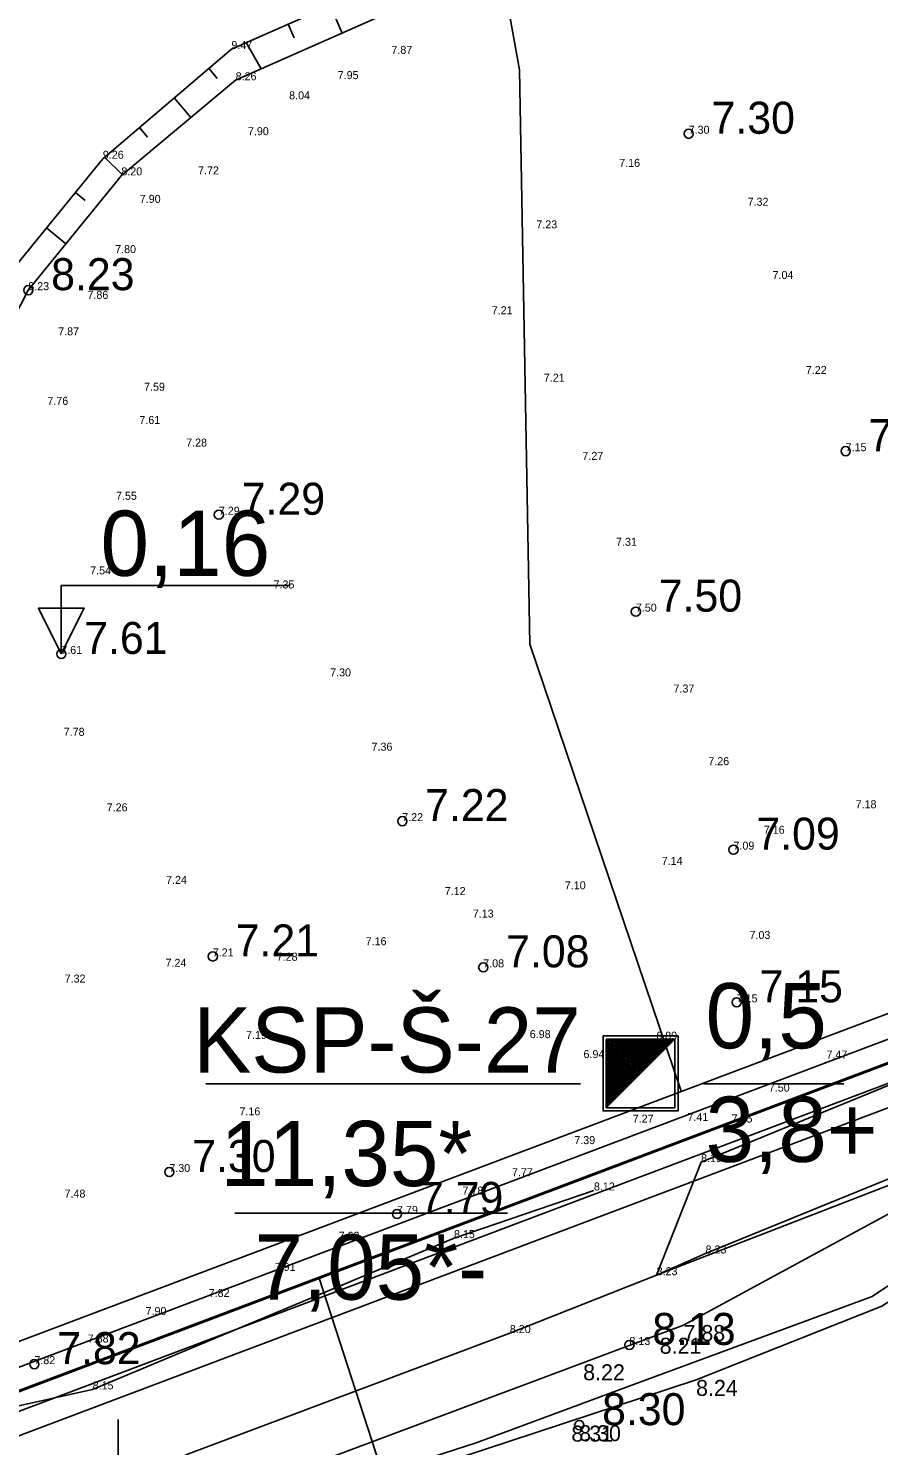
# Model space of a CAD drawing. Extents: x 433497 to 434382, y 6534486 to 6534993.
# Drawn here: x 433896.1 to 433933.2, y 6534702.9 to 6534764.8 of the extents above; entities that cross this region are included whole.
import ezdxf

# ---------------------------------------------------------------- set-up
doc = ezdxf.new("R2010")
doc.units = 0
for name, color, linetype in [('Default', 7, 'Continuous'), ('GEOLPUNKT', 7, 'Continuous'), ('jääkpaksus', 7, 'Continuous'), ('kataster', 7, 'Continuous'), ('KORGUS-EH2000', 7, 'Continuous'), ('MOOTKORG-EH2000', 7, 'Continuous'), ('PIIR', 7, 'Continuous'), ('RELJEEF', 7, 'Continuous'), ('VEEKOGU', 7, 'Continuous'), ('VORK', 7, 'Continuous')]:
    doc.layers.add(name, color=color, linetype=linetype)

msp = doc.modelspace()

# ---------------------------------------------------------------- linework, layer by layer
at = {"layer": 'Default'}
msp.add_lwpolyline([(433617.12, 6534791.025), (433632.75, 6534606.045), (434137.38, 6534796.515), (434127.69, 6534855.6), (433968.21, 6534911.925), (433942.38, 6534904.035), (433920.99, 6534907.275)], close=True, dxfattribs=at)
msp.add_lwpolyline([(433617.12, 6534791.025), (433632.75, 6534606.045), (434137.38, 6534796.515), (434127.69, 6534855.6), (433968.21, 6534911.925), (433942.38, 6534904.035), (433920.99, 6534907.275)], close=True, dxfattribs=at)
msp.add_lwpolyline([(433617.12, 6534791.025), (433632.75, 6534606.045), (434137.38, 6534796.515), (434127.69, 6534855.6), (433968.21, 6534911.925), (433942.38, 6534904.035), (433920.99, 6534907.275)], close=True, dxfattribs=at)
at = {"layer": 'GEOLPUNKT'}
for p, q in [((433921.332, 6534717.624), (433924.332, 6534720.624)), ((433921.332, 6534717.654), (433924.302, 6534720.624)), ((433921.332, 6534717.725), (433924.231, 6534720.624)), ((433921.332, 6534717.795), (433924.161, 6534720.624)), ((433921.332, 6534717.866), (433924.09, 6534720.624)), ((433921.332, 6534717.937), (433924.019, 6534720.624)), ((433921.332, 6534718.008), (433923.948, 6534720.624)), ((433921.332, 6534718.078), (433923.878, 6534720.624)), ((433921.332, 6534718.149), (433923.807, 6534720.624)), ((433921.332, 6534718.22), (433923.736, 6534720.624)), ((433921.332, 6534718.29), (433923.666, 6534720.624)), ((433921.332, 6534718.361), (433923.595, 6534720.624)), ((433921.332, 6534718.432), (433923.524, 6534720.624)), ((433921.332, 6534718.503), (433923.453, 6534720.624)), ((433921.332, 6534718.573), (433923.383, 6534720.624)), ((433921.332, 6534718.644), (433923.312, 6534720.624)), ((433921.332, 6534718.715), (433923.241, 6534720.624)), ((433921.332, 6534718.785), (433923.171, 6534720.624)), ((433921.332, 6534718.856), (433923.1, 6534720.624)), ((433921.332, 6534718.927), (433923.029, 6534720.624)), ((433921.332, 6534718.998), (433922.959, 6534720.624)), ((433921.332, 6534719.068), (433922.888, 6534720.624)), ((433921.332, 6534719.139), (433922.817, 6534720.624)), ((433921.332, 6534719.21), (433922.746, 6534720.624)), ((433921.332, 6534719.28), (433922.676, 6534720.624)), ((433921.332, 6534719.351), (433922.605, 6534720.624)), ((433921.332, 6534719.422), (433922.534, 6534720.624)), ((433921.332, 6534719.492), (433922.464, 6534720.624)), ((433921.332, 6534719.563), (433922.393, 6534720.624)), ((433921.332, 6534719.634), (433922.322, 6534720.624)), ((433921.332, 6534719.705), (433922.251, 6534720.624)), ((433921.332, 6534719.775), (433922.181, 6534720.624)), ((433921.332, 6534719.846), (433922.11, 6534720.624)), ((433921.332, 6534719.917), (433922.039, 6534720.624)), ((433921.332, 6534719.987), (433921.969, 6534720.624)), ((433921.332, 6534720.058), (433921.898, 6534720.624)), ((433921.332, 6534720.129), (433921.827, 6534720.624)), ((433921.332, 6534720.2), (433921.756, 6534720.624)), ((433921.332, 6534720.27), (433921.686, 6534720.624)), ((433921.332, 6534720.341), (433921.615, 6534720.624)), ((433921.332, 6534720.412), (433921.544, 6534720.624)), ((433921.332, 6534720.482), (433921.474, 6534720.624)), ((433921.332, 6534720.553), (433921.403, 6534720.624)), ((433922.832, 6534719.124), (433922.832, 6534719.124))]:
    msp.add_line(p, q, dxfattribs=at)
for points in [[(433921.191, 6534720.765), (433924.473, 6534720.765), (433924.473, 6534717.483), (433921.191, 6534717.483)], [(433921.332, 6534720.624), (433924.332, 6534720.624), (433924.332, 6534717.624), (433921.332, 6534717.624)]]:
    msp.add_lwpolyline(points, close=True, dxfattribs=at)
for points in [[(433903.825, 6534718.667), (433920.21, 6534718.667)], [(433925.589, 6534718.667), (433931.717, 6534718.667)], [(433905.096, 6534713.013), (433917.013, 6534713.013)]]:
    msp.add_lwpolyline(points, dxfattribs=at)
at = {"layer": 'jääkpaksus'}
msp.add_lwpolyline([(433897.514, 6534737.465), (433897.514, 6534740.465), (433907.514, 6534740.465)], dxfattribs=at)
msp.add_lwpolyline([(433897.514, 6534737.465), (433896.514, 6534739.465), (433898.514, 6534739.465)], close=True, dxfattribs=at)
at = {"layer": 'kataster'}
msp.add_lwpolyline([(433617.102, 6534791.002), (433632.769, 6534606.029), (434137.446, 6534796.469), (434127.827, 6534855.589), (433950.026, 6534918.39)], close=True, dxfattribs=at)
at = {"layer": 'KORGUS-EH2000'}
for centre in [(433924.936, 6534760.209), (433896.07, 6534753.37), (433931.794, 6534746.331), (433904.401, 6534743.551), (433922.627, 6534739.316), (433897.514, 6534737.465), (433912.416, 6534730.156), (433926.894, 6534728.909), (433904.135, 6534724.24), (433915.956, 6534723.763), (433927.033, 6534722.233), (433902.237, 6534714.815), (433912.189, 6534712.982), (433922.346, 6534707.253), (433896.337, 6534706.413), (433920.152, 6534703.746)]:
    msp.add_circle(centre, 0.2, dxfattribs=at)
at = {"layer": 'PIIR'}
msp.add_line((433908.78, 6534710.175), (433926.99, 6534654.105), dxfattribs=at)
for points in [[(433632.021, 6534604.835), (434138.248, 6534795.936), (434128.468, 6534856.135), (433968.226, 6534912.818), (433942.33, 6534904.85), (433920.952, 6534908.165), (433616.327, 6534791.524), (433632.021, 6534604.835)], [(433632.732, 6534605.959), (434137.353, 6534796.454), (434127.754, 6534855.539), (433968.208, 6534911.976), (433942.39, 6534904.031), (433921.04, 6534907.341), (433617.174, 6534790.992), (433632.732, 6534605.959)], [(433924.608, 6534718.343), (433917.99, 6534737.895), (433917.54, 6534763.005), (433913.58, 6534784.995), (433921.17, 6534796.005), (433926.99, 6534825.75), (433941, 6534841.965), (433961.01, 6534846.975), (433983.99, 6534835.44), (434035.235, 6534886.132)], [(433633.446, 6534604.304), (434134.891, 6534793.6)]]:
    msp.add_lwpolyline(points, dxfattribs=at)
for points in [[(433618.234, 6534790.327), (433921.149, 6534906.313), (433942.464, 6534903.008), (433968.187, 6534910.923), (434126.862, 6534854.794), (434136.235, 6534797.101), (433633.617, 6534607.362)], [(433619.24, 6534789.695), (433634.52, 6534608.851), (434135.141, 6534797.808), (434125.908, 6534854.108), (433968.165, 6534909.82), (433942.53, 6534901.99), (433921.212, 6534905.219)], [(433619.24, 6534789.695), (433634.52, 6534608.851), (434135.141, 6534797.808), (434125.908, 6534854.108), (433968.165, 6534909.82), (433942.53, 6534901.99), (433921.212, 6534905.219)]]:
    msp.add_lwpolyline(points, close=True, dxfattribs=at)
at = {"layer": 'RELJEEF'}
for p, q in [((433909.26, 6534765.814), (433909.789, 6534764.614)), ((433907.695, 6534764.405), (433907.43, 6534765.008)), ((433905.6, 6534764.201), (433906.247, 6534763.041)), ((433904.32, 6534762.62), (433903.969, 6534763.077)), ((433902.448, 6534761.779), (433903.18, 6534760.921)), ((433901.285, 6534760.06), (433900.927, 6534760.48)), ((433899.405, 6534759.181), (433900.178, 6534758.421)), ((433898.553, 6534757.297), (433898.132, 6534757.641)), ((433896.871, 6534756.089), (433897.717, 6534755.402))]:
    msp.add_line(p, q, dxfattribs=at)
for points in [[(433836.51, 6534724.993), (433839.722, 6534730.314), (433843.112, 6534725.867), (433850.656, 6534716.817), (433853.509, 6534713.897), (433858.468, 6534710.165), (433861.177, 6534707.751), (433868.295, 6534708.365), (433869.862, 6534699.668), (433872.606, 6534698.155), (433880.692, 6534699.223), (433884.244, 6534701.553), (433886.906, 6534704.949), (433887.082, 6534708.682), (433884.587, 6534710.617), (433878.791, 6534711.468), (433877.958, 6534723.638), (433880.96, 6534728.715), (433884.3, 6534732.983), (433888.143, 6534739.195), (433895.061, 6534753.859), (433899.33, 6534759.117), (433904.949, 6534763.914), (433915.987, 6534768.78)], [(433916.484, 6534767.586), (433905.134, 6534762.547), (433900.139, 6534758.389), (433896.07, 6534753.37), (433888.649, 6534738.904), (433884.83, 6534732.743), (433882.198, 6534728.762), (433878.824, 6534723.659), (433880.307, 6534718.793), (433879.693, 6534713.136), (433882.886, 6534712.985), (433885.317, 6534711.447), (433888.963, 6534708.91), (433888.001, 6534707.482), (433887.582, 6534705.196), (433885.049, 6534700.668), (433881.086, 6534698.719), (433871.506, 6534696.924), (433869.679, 6534698.635), (433868.465, 6534701.335), (433868.104, 6534706.14), (433860.946, 6534706.997), (433858.426, 6534708.55), (433852.899, 6534712.846)], [(433899.928, 6534663.45), (433900.517, 6534670.895), (433900.924, 6534685.936), (433902.788, 6534688.926), (433901.443, 6534693.211), (433900.914, 6534697.707), (433925.259, 6534705.724), (433933.384, 6534708.942), (433941.076, 6534713.927), (433958.256, 6534720.818), (433999.504, 6534737.335), (434040.692, 6534753.828), (434042.383, 6534754.563)], [(433925.479, 6534715.247), (433937.845, 6534720.314), (433943.299, 6534721.644), (433950.416, 6534724.88), (433956.745, 6534727.703), (433973.189, 6534734.3), (433987.35, 6534739.823), (433991.837, 6534741.367)], [(433887.582, 6534705.196), (433890.236, 6534703.163), (433893.451, 6534704.108), (433898.883, 6534705.309), (433914.68, 6534711.923), (433920.793, 6534714.007)]]:
    msp.add_lwpolyline(points, dxfattribs=at)
at = {"layer": 'VEEKOGU'}
msp.add_line((433923.536, 6534710.303), (433925.479, 6534715.247), dxfattribs=at)
for points in [[(433871.506, 6534696.924), (433881.086, 6534698.719), (433885.049, 6534700.668), (433887.582, 6534705.196), (433888.001, 6534707.482), (433888.963, 6534708.91), (433885.317, 6534711.447), (433882.886, 6534712.985), (433879.693, 6534713.136), (433880.307, 6534718.793), (433878.824, 6534723.659), (433882.198, 6534728.762), (433884.83, 6534732.743), (433888.649, 6534738.904), (433896.07, 6534753.37), (433900.139, 6534758.389), (433905.134, 6534762.547), (433916.484, 6534767.586)], [(433916.484, 6534767.586), (433905.134, 6534762.547), (433900.139, 6534758.389), (433896.07, 6534753.37), (433888.649, 6534738.904), (433884.83, 6534732.743), (433882.198, 6534728.762), (433878.824, 6534723.659), (433880.307, 6534718.793), (433879.693, 6534713.136), (433882.886, 6534712.985), (433885.317, 6534711.447), (433888.963, 6534708.91), (433888.001, 6534707.482), (433887.582, 6534705.196), (433885.049, 6534700.668)], [(433898.23, 6534663.727), (433899.607, 6534697.038), (433900.708, 6534699.122), (433924.709, 6534708.124), (433937.253, 6534714.919), (433957.997, 6534721.463), (433975.446, 6534730.696), (433987.3, 6534735.407), (433998.265, 6534739.968), (434019.672, 6534748.507), (434048.697, 6534758.47), (434049.568, 6534761.922), (434049.568, 6534761.922), (434049.568, 6534761.922)], [(434044.29, 6534759.958), (434037.841, 6534756.644), (434028.818, 6534752.575), (434020.612, 6534749.574), (434001.837, 6534742.708), (433986.897, 6534737.245), (433977.532, 6534732.603), (433960.547, 6534725.703), (433951.026, 6534721.836), (433940.287, 6534716.784), (433923.536, 6534710.303)], [(433925.479, 6534715.247), (433937.845, 6534720.314), (433943.299, 6534721.644), (433950.416, 6534724.88), (433956.745, 6534727.703), (433973.189, 6534734.3), (433987.35, 6534739.823), (433991.837, 6534741.367), (434002.667, 6534744.979), (434017.66, 6534750.309), (434019.823, 6534750.58), (434028.267, 6534753.988), (434032.895, 6534755.564), (434036.92, 6534757.793), (434044.29, 6534759.958)], [(433925.672, 6534711.253), (433940.078, 6534717.122), (433949.828, 6534721.635), (433956.983, 6534724.796), (433974.334, 6534731.734), (433986.402, 6534737.901), (434023.734, 6534750.878)], [(433845.74, 6534684.471), (433860.498, 6534689.801), (433878.502, 6534693.682), (433889.603, 6534697.413), (433895.281, 6534698.972), (433896.571, 6534697.665), (433897.112, 6534693.509), (433896.553, 6534689.981), (433896.343, 6534685.933), (433896.283, 6534673.748), (433896.229, 6534662.913), (433899.798, 6534662.895), (433899.858, 6534675.039), (433899.932, 6534689.992), (433900.852, 6534698.199), (433915.648, 6534702.98), (433922.291, 6534705.432), (433932.948, 6534709.366), (433940.179, 6534714.231)], [(433925.672, 6534711.253), (433923.536, 6534710.303), (433917.119, 6534707.774), (433903.078, 6534702.488), (433898.531, 6534700.346), (433895.329, 6534701.275), (433892.54, 6534702.862), (433885.584, 6534700.735), (433885.049, 6534700.668)]]:
    msp.add_lwpolyline(points, dxfattribs=at)
at = {"layer": 'VORK'}
msp.add_line((433900, 6534704), (433900, 6534696), dxfattribs=at)

# ---------------------------------------------------------------- texts
at = {"layer": 'GEOLPUNKT'}
for s, p in [('KSP-Š-27', (433903.275, 6534719.164)), ('0,5', (433925.674, 6534720.223)), ('3,8+', (433925.674, 6534715.258)), ('11,35*', (433904.46, 6534714.199)), ('7,05*-', (433905.957, 6534709.233))]:
    msp.add_text(s, height=2.85, dxfattribs=at).set_placement(p)
at = {"layer": 'jääkpaksus'}
msp.add_text(' 0,16', height=2.85, rotation=360, dxfattribs=at).set_placement((433898.169, 6534740.88))
at = {"layer": 'KORGUS-EH2000'}
for s, p in [('7.30', (433925.936, 6534760.209)), ('8.23', (433897.07, 6534753.37)), ('7.15', (433932.794, 6534746.331)), ('7.29', (433905.401, 6534743.551)), ('7.50', (433923.627, 6534739.316)), ('7.61', (433898.514, 6534737.465)), ('7.22', (433913.416, 6534730.156)), ('7.09', (433927.894, 6534728.909)), ('7.21', (433905.135, 6534724.24)), ('7.08', (433916.956, 6534723.763)), ('7.15', (433928.033, 6534722.233)), ('7.30', (433903.237, 6534714.815)), ('7.79', (433913.189, 6534712.982)), ('8.13', (433923.346, 6534707.253)), ('7.82', (433897.337, 6534706.413)), ('8.30', (433921.152, 6534703.746))]:
    msp.add_text(s, height=1.4, dxfattribs=at).set_placement(p)
at = {"layer": 'MOOTKORG-EH2000'}
for s, height, p in [('9.47', 0.35, (433904.949, 6534763.914)), ('7.87', 0.35, (433911.942, 6534763.701)), ('7.95', 0.35, (433909.595, 6534762.598)), ('8.26', 0.35, (433905.134, 6534762.547)), ('8.04', 0.35, (433907.474, 6534761.712)), ('7.90', 0.35, (433905.671, 6534760.147)), ('7.30', 0.35, (433924.936, 6534760.209)), ('9.26', 0.35, (433899.33, 6534759.117)), ('8.20', 0.35, (433900.139, 6534758.389)), ('7.72', 0.35, (433903.491, 6534758.432)), ('7.16', 0.35, (433921.901, 6534758.761)), ('7.90', 0.35, (433900.944, 6534757.188)), ('7.32', 0.35, (433927.512, 6534757.062)), ('7.23', 0.35, (433918.277, 6534756.073)), ('7.80', 0.35, (433899.869, 6534754.992)), ('8.23', 0.35, (433896.07, 6534753.37)), ('7.04', 0.35, (433928.601, 6534753.86)), ('7.86', 0.35, (433898.658, 6534752.99)), ('7.21', 0.35, (433916.329, 6534752.319)), ('7.87', 0.35, (433897.38, 6534751.397)), ('7.22', 0.35, (433930.057, 6534749.705)), ('7.59', 0.35, (433901.132, 6534748.974)), ('7.21', 0.35, (433918.605, 6534749.368)), ('7.76', 0.35, (433896.907, 6534748.356)), ('7.61', 0.35, (433900.926, 6534747.519)), ('7.28', 0.35, (433902.972, 6534746.533)), ('7.27', 0.35, (433920.29, 6534745.951)), ('7.15', 0.35, (433931.794, 6534746.331)), ('7.55', 0.35, (433899.906, 6534744.205)), ('7.29', 0.35, (433904.401, 6534743.551)), ('7.31', 0.35, (433921.76, 6534742.194)), ('7.54', 0.35, (433898.777, 6534740.946)), ('7.35', 0.35, (433906.791, 6534740.328)), ('7.50', 0.35, (433922.627, 6534739.316)), ('7.61', 0.35, (433897.514, 6534737.465)), ('7.30', 0.35, (433909.265, 6534736.484)), ('7.37', 0.35, (433924.272, 6534735.779)), ('7.78', 0.35, (433897.62, 6534733.886)), ('7.36', 0.35, (433911.075, 6534733.237)), ('7.26', 0.35, (433925.794, 6534732.601)), ('7.26', 0.35, (433899.499, 6534730.585)), ('7.18', 0.35, (433932.233, 6534730.718)), ('7.22', 0.35, (433912.416, 6534730.156)), ('7.16', 0.35, (433928.219, 6534729.603)), ('7.09', 0.35, (433926.894, 6534728.909)), ('7.14', 0.35, (433923.755, 6534728.241)), ('7.24', 0.35, (433902.094, 6534727.413)), ('7.12', 0.35, (433914.274, 6534726.924)), ('7.10', 0.35, (433919.523, 6534727.175)), ('7.13', 0.35, (433915.501, 6534725.939)), ('7.03', 0.35, (433927.594, 6534725.004)), ('7.21', 0.35, (433904.135, 6534724.24)), ('7.16', 0.35, (433910.818, 6534724.73)), ('7.24', 0.35, (433902.07, 6534723.786)), ('7.28', 0.35, (433906.93, 6534724.05)), ('7.08', 0.35, (433915.956, 6534723.763)), ('7.32', 0.35, (433897.661, 6534723.097)), ('7.15', 0.35, (433927.033, 6534722.233)), ('7.19', 0.35, (433905.587, 6534720.632)), ('6.98', 0.35, (433917.99, 6534720.668)), ('6.89', 0.35, (433923.521, 6534720.599)), ('6.94', 0.35, (433920.339, 6534719.796)), ('7.47', 0.35, (433930.959, 6534719.772)), ('7.50', 0.35, (433928.439, 6534718.328)), ('7.16', 0.35, (433905.302, 6534717.291)), ('7.27', 0.35, (433922.491, 6534716.972)), ('7.41', 0.35, (433924.884, 6534717.045)), ('7.85', 0.35, (433926.811, 6534716.979)), ('7.39', 0.35, (433919.938, 6534716.034)), ('8.19', 0.35, (433925.479, 6534715.247)), ('7.30', 0.35, (433902.237, 6534714.815)), ('7.77', 0.35, (433917.213, 6534714.632)), ('7.48', 0.35, (433897.656, 6534713.696)), ('7.78', 0.35, (433915.048, 6534713.827)), ('8.12', 0.35, (433920.793, 6534714.007)), ('7.79', 0.35, (433912.189, 6534712.982)), ('7.62', 0.35, (433909.636, 6534711.851)), ('8.15', 0.35, (433914.68, 6534711.923)), ('8.23', 0.35, (433925.672, 6534711.253)), ('7.91', 0.35, (433906.839, 6534710.491)), ('8.23', 0.35, (433923.536, 6534710.303)), ('7.82', 0.35, (433903.957, 6534709.349)), ('7.90', 0.35, (433901.198, 6534708.563)), ('8.20', 0.35, (433917.119, 6534707.774)), ('7.88', 0.7, (433924.709, 6534707.424)), ('7.88', 0.35, (433898.669, 6534707.36)), ('8.13', 0.35, (433922.346, 6534707.253)), ('8.21', 0.7, (433923.669, 6534706.868)), ('7.82', 0.35, (433896.337, 6534706.413)), ('8.22', 0.7, (433920.324, 6534705.708)), ('8.15', 0.35, (433898.883, 6534705.309)), ('8.24', 0.7, (433925.259, 6534705.024)), ('8.31', 0.7, (433919.809, 6534703.026)), ('8.30', 0.7, (433920.152, 6534703.046))]:
    msp.add_text(s, height=height, dxfattribs=at).set_placement(p)

doc.saveas('drawing.dxf')
